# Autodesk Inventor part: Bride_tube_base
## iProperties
Shininess: 64.0
Length Units: 11269
Angle Units: 11279
Time Units: 11290
Mass Units: 11283
Length Display Precision: 3
Angle Display Precision: 2
Compacted: True
Part Number: Bride_tube_base
Document SubType Name: Modeling
Created: 2008-02
Material: Acier inoxydable, austénitique
Designer: Pascal
Density: 0.0
Volumn: 0.0
Area: 0.0
PropertySet Name: Model Information
Control State: 0
Master: False
Checked Out: False
DESIGNATION: Bride tube corps
Author: Pascal
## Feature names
1. Extrusion1
2. Extrusion2
3. Réseau circulaire1 [Circular Pattern]
4. Extrusion3
